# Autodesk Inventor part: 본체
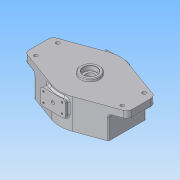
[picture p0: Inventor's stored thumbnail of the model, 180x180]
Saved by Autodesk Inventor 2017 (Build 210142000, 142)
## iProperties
Part Number: 본체
Material: 일반
Document SubType Name: Modeling
Designer: mrc
Density: 1 g/cm^3
Appearance: 기본값
Author: mrc
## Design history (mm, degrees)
sketch "스케치1"
  geometry: L1 (0, 94)-(0, -94); L2 (-24.317, 94)-(24.317, 94); L3 (51.683, 18.811)-(24.317, 94); L4 (-51.683, 18.811)-(-24.317, 94); L5 (-24.317, -94)-(24.317, -94); L6 (51.683, -18.811)-(24.317, -94); L7 (-51.683, -18.811)-(-24.317, -94); L8 (0, 68)-(0, -68); L9 (-33.78, 68)-(33.78, 68); L10 (-33.78, -68)-(33.78, -68); A1 r 55 centre (0, 0) between (-51.683, -18.811) and (51.683, -18.811); A2 r 55 centre (0, 0) between (-51.683, 18.811) and (-51.683, -18.811); A3 r 55 centre (0, 0) between (51.683, 18.811) and (-51.683, 18.811); A4 r 55 centre (0, 0) between (51.683, -18.811) and (51.683, 18.811); 2 further points
  constraints: 20 end point, 11 tangent, 9 point on circle, 5 midpoint, 4 centre point, 4 point on line, 3 horizontal, 2 coincident, 2 vertical, 1 parallel
  dimensions: "d0" = 110 diameter of A1; "d1" = 188 distance of L1.start L1.end; "d2" = 40 deg angle of L3 L4; "d3" = 20 deg angle of L1 L3; "d4" = 40 deg angle of L6 L7; "d5" = 20 deg angle of L1 L6; "d6" = 136 distance of L8.start L8.end; "d7" = 136 distance between parallel lines of L10 L9; "d8" = 26 distance between parallel lines of L5 L10
extrude "돌출1" new body sketch "스케치1" distance "d9" = 15; taper "d10" = 0 deg
extrude "돌출2" join sketch "스케치1" distance "d11" = 55; taper "d12" = 0 deg
sketch "스케치2"
  geometry: L1 (94, 0)-(-94, 0) reference; L2 (-94, 0)-(-94, 15) reference; L3 (-94, 15)-(-68, 15) reference; L4 (-68, 15)-(-68, 55) reference; L5 (-68, 55)-(68, 55) reference; L6 (68, 55)-(68, 15) reference; L7 (68, 15)-(94, 15) reference; L8 (94, 15)-(94, 0) reference; L9 (0, 0)-(0, 55); L10 (-32, 5)-(14, 5); L11 (14, 5)-(14, 35); L12 (14, 35)-(-32, 35); L13 (-32, 35)-(-32, 5); L14 (-32, 5)-(14, 35); L15 (14, 5)-(-32, 35); L16 (-9, 5)-(-9, 35); L17 (14, 20)-(-32, 20)
  constraints: 18 end point, 5 midpoint, 2 parallel, 1 horizontal, 1 perpendicular
  dimensions: "d13" = 46 distance of L12.end L11.end; "d14" = 30 distance of L11.end L10.end; "d122" = 9 distance between parallel lines of L9 L16; "d123" = 20 distance between parallel lines of L1 L17
extrude "돌출3" join sketch "스케치2" stored distance "d16" = 118; taper "d17" = 0 deg
sketch "스케치3"
  geometry: C1 r 17.5 at (0, 0); A1 r 55 centre (0, 0) between (51.683, -18.811) and (51.683, 18.811) reference
  constraints: 2 coincident, 1 centre point
  dimensions: "d18" = 35 diameter of C1
extrude "돌출4" join sketch "스케치3" distance "d20" = 5; taper "d21" = 0 deg
sketch "스케치4"
  geometry: L1 (55, 0)-(-55, 0); A1 r 55 centre (0, 0) between (51.683, -18.811) and (51.683, 18.811) reference; A2 r 55 centre (0, 0) between (-51.683, 18.811) and (-51.683, -18.811) reference; 4 further points
  constraints: 2 end point, 2 point on circle, 2 symmetric about line, 1 horizontal alignment
  dimensions: "d22" = 40 distance of point (20, -79) point (-20, -79); "d23" = 79 vertical distance of A1.centre point (-20, -79); "d24" = 20 horizontal distance of A1.centre point (-20, -79)
hole "구멍1" sketch "스케치4" at (20, -79), (-20, -79), (-20, 79), (20, 79) diameter "d25" = 6.6; stored, may be unused: countersink angle "d29" = 90 deg, drill point angle "d31" = 118 deg; dims "d26" = 6, "d27" = 4, "d28" = 2, "d30" = 8
sketch "스케치5"
  geometry: C1 r 3.3 at (-20, -79) reference; C2 r 3.3 at (20, -79) reference; 1 further point
hole "구멍2" sketch "스케치5" at (20, -79), (-20, -79) diameter "d32" = 11; stored, may be unused: countersink angle "d36" = 90 deg, drill point angle "d38" = 118 deg; dims "d33" = 6, "d34" = 4, "d35" = 2, "d37" = 6.6
sketch "스케치6"
  geometry: C1 r 3.3 at (20, 79) reference; C2 r 3.3 at (-20, 79) reference; 1 further point
hole "구멍3" sketch "스케치6" at (20, 79), (-20, 79) diameter "d39" = 11; stored, may be unused: countersink angle "d43" = 90 deg, drill point angle "d45" = 0 deg; dims "d40" = 6, "d41" = 4, "d42" = 2, "d44" = 6.6
sketch "스케치7"
  geometry: L1 (5, 14)-(5, -32) reference; L2 (11, -26)-(29, -26); L3 (29, -26)-(29, 8); L4 (29, 8)-(11, 8); L5 (11, 8)-(11, -26); L6 (11, -26)-(29, 8); L7 (29, -26)-(11, 8); L8 (29, -9)-(11, -9); L9 (20, -26)-(20, 8); 5 further points
  constraints: 16 end point, 4 coincident, 4 midpoint, 2 parallel, 1 horizontal, 1 perpendicular
  dimensions: "d46" = 18 distance of L4.end L3.end; "d47" = 34 distance of L3.end L2.end; "d48" = 6 distance between parallel lines of L1 L5; "d124" = 9 distance from line of point (0, 0) L8
hole "구멍4" sketch "스케치7" at (11, -26), (11, 8), (29, 8), (29, -26) diameter "d49" = 3.242; stored, may be unused: countersink angle "d53" = 90 deg, drill point angle "d55" = 118 deg; dims "d50" = 8, "d51" = 4, "d52" = 2, "d54" = 10
sketch "스케치8"
  geometry: L1 (55, 0)-(-55, 0); A1 r 55 centre (0, 0) between (-51.683, 18.811) and (-51.683, -18.811) reference; A2 r 55 centre (0, 0) between (51.683, -18.811) and (51.683, 18.811) reference; 4 further points
  constraints: 2 end point, 2 point on circle, 2 symmetric about line
  dimensions: "d56" = 50 distance of point (-25, -61) point (25, -61); "d57" = 25 horizontal distance of A1.centre point (-25, -61); "d58" = 61 vertical distance of A1.centre point (-25, -61)
hole "구멍5" sketch "스케치8" at (25, -61), (-25, -61), (-25, 61), (25, 61) diameter "d59" = 4.917; stored, may be unused: countersink angle "d63" = 90 deg, drill point angle "d65" = 118 deg; dims "d60" = 12, "d61" = 4, "d62" = 2, "d64" = 14
sketch "스케치9"
  geometry: L1 (68, 55)-(68, 15) reference; L2 (68, 15)-(94, 15) reference; L3 (94, 15)-(94, 0) reference; L4 (94, 0)-(17.5, 0) reference; L5 (17.5, 0)-(17.5, -5) reference; L6 (17.5, -5)-(-17.5, -5) reference; L7 (-17.5, -5)-(-17.5, 0) reference; L8 (-17.5, 0)-(-94, 0) reference; L9 (-94, 0)-(-94, 15) reference; L10 (-94, 15)-(-68, 15) reference; L11 (-68, 15)-(-68, 55) reference; L12 (-68, 55)-(68, 55) reference; L13 (18.811, 55)-(-18.811, 55) reference; L14 (0, 55)-(0, 25); L15 (0, 55)-(-40, 55); L16 (-68, 55)-(-18.811, 55) reference; L17 (-40, 55)-(-40, 25); L18 (-40, 25)-(0, 25); 1 further point
  constraints: 8 end point, 2 perpendicular, 1 midpoint, 1 point on line, 1 vertical
  dimensions: "d66" = 30 distance of L14.start L14.end; "d67" = 40 distance of L14.start L15.end
revolve "회전1" sketch "스케치9" stored, may be unused: angle "d68" = 90 deg
sketch "스케치10"
  geometry: L1 (68, 55)-(68, 15) reference; L2 (68, 15)-(94, 15) reference; L3 (94, 15)-(94, 0) reference; L4 (94, 0)-(17.5, 0) reference; L5 (17.5, 0)-(17.5, -5) reference; L6 (17.5, -5)-(-17.5, -5) reference; L7 (-17.5, -5)-(-17.5, 0) reference; L8 (-17.5, 0)-(-94, 0) reference; L9 (-94, 0)-(-94, 15) reference; L10 (-94, 15)-(-68, 15) reference; L11 (-68, 15)-(-68, 55) reference; L12 (-68, 55)-(-40, 55) reference; L13 (-40, 55)-(-40, 25) reference; L14 (-40, 25)-(40, 25) reference; L15 (40, 25)-(40, 55) reference; L16 (40, 55)-(68, 55) reference; L17 (0, 25)-(0, -5); L18 (0, 25)-(-10, 25); L19 (40, 25)-(-40, 25) reference; L20 (-10, 25)-(-10, 15); L21 (-10, 15)-(-8, 15); L22 (-8, 15)-(-8, 3.4); L23 (-8, 3.4)-(-12.5, 3.4); L24 (-12.5, 3.4)-(-12.5, -5); L25 (-12.5, -5)-(0, -5); 1 further point
  constraints: 16 end point, 5 perpendicular, 2 midpoint, 2 point on line, 2 vertical
  dimensions: "d71" = 20 diameter of L20 L17; "d72" = 16 diameter of L22 L17; "d73" = 10 distance of L18.end L20.end; "d74" = 25 diameter of L24 L17; "d75" = 8.4 distance of L23.end L24.end
revolve "회전2" sketch "스케치10" stored, may be unused: angle "d76" = 90 deg
sketch "스케치11"
  geometry: C1 r 10 at (0, 0) reference; C2 r 40 at (0, 0) reference; 2 further points
  constraints: 1 horizontal alignment
  dimensions: "d77" = 30 distance of point (15, -26) point (-15, -26); "d78" = 15 horizontal distance of C2.centre point (15, -26); "d79" = 26 vertical distance of C1.centre point (15, -26)
hole "구멍6" sketch "스케치11" at (15, -26), (-15, -26) diameter "d80" = 3.242; stored, may be unused: countersink angle "d84" = 90 deg, drill point angle "d86" = 118 deg; dims "d81" = 8, "d82" = 4, "d83" = 2, "d85" = 10
sketch "스케치14"
  geometry: C1 r 47.5 at (0, 0); C2 r 43.4 at (0, 0); A1 r 55 centre (0, 0) between (51.683, -18.811) and (51.683, 18.811) reference
  constraints: 2 centre point, 1 coincident
  dimensions: "d99" = 95 diameter of C1; "d100" = 4.1 radial gap between concentric circles of C1 C2
extrude "돌출7" cut sketch "스케치14" distance "d101" = 2.4; taper "d102" = 0 deg
fillet "모깎기1" dims "d103" = 10
chamfer "모따기1" distance "d106" = 1; stored, may be unused: second distance "d107" = 2, angle "d108" = 45 deg
fillet "모깎기4" dims "d109" = 0.5
fillet "모깎기5" dims "d110" = 5
fillet "모깎기6" dims "d111" = 0.2
chamfer "모따기2" distance "d112" = 0.4; stored, may be unused: second distance "d113" = 2, angle "d114" = 30 deg
fillet "모깎기7" dims "d115" = 3
fillet "모깎기8" dims "d116" = 3
fillet "모깎기9" dims "d117" = 3
sketch "스케치15" dims "d11" = 55
  geometry: L1 (0, 37)-(63.358, 37) reference; L2 (56.567, 18.398)-(6.792, 18.398); L3 (6.792, 18.398)-(6.792, 25.602); L4 (6.792, 25.602)-(56.567, 25.602); L5 (56.567, 25.602)-(56.567, 18.398); L6 (56.567, 22)-(6.792, 22); L7 (31.679, 18.398)-(31.679, 25.602); L8 (90.679, 12)-(90.679, -8) reference; 1 further point
  constraints: 4 end point, 4 midpoint, 2 other
  dimensions: "d118" = 59 distance between parallel lines of L8 L7; "d119" = 15 distance between parallel lines of L1 L6
feature "엠보싱1" sketch "스케치15" dims "d0" = 110, "d1" = 188, "d2" = 40 deg, "d3" = 20 deg, "d4" = 40 deg, "d5" = 20 deg, "d7" = 136, "d8" = 26, "d120" = 0.5, "d121" = 0
sketch "스케치16"
  geometry: L1 (59, 9)-(59, -27) reference; L2 (59, -9)-(-59, -9); L3 (-59, 9)-(-59, -27) reference; L4 (28.373, -15)-(18.735, -15); L5 (28.373, -3)-(23.812, -3); L6 (18.735, -15)-(-18.735, -15); L7 (-18.735, -15)-(-28.373, -15); L8 (-23.812, -3)-(-28.373, -3); L9 (23.812, -3)-(-23.812, -3); C1 r 40 at (0, 0) reference; A1 r 24 centre (0, 0) between (23.812, -3) and (-23.812, -3); A2 r 29 centre (0, -9) between (28.373, -3) and (-28.373, -3); A3 r 24 centre (0, 0) between (22.249, -9) and (23.812, -3); A4 r 29 centre (0, -9) between (29, -9) and (28.373, -3); A5 r 29 centre (0, -9) between (28.373, -15) and (29, -9); A6 r 24 centre (0, 0) between (-18.735, -15) and (18.735, -15); A7 r 24 centre (0, 0) between (-23.812, -3) and (-18.735, -15); A8 r 29 centre (0, -9) between (-28.373, -15) and (28.373, -15); A9 r 29 centre (0, -9) between (-28.373, -3) and (-28.373, -15); A10 r 24 centre (0, 0) between (18.735, -15) and (22.249, -9)
  constraints: 25 point on circle, 14 end point, 10 centre point, 3 horizontal, 3 midpoint, 2 point on line, 1 coincident
  dimensions: "d127" = 48 diameter of A1; "d128" = 58 diameter of A2; "d129" = 12 distance between parallel lines of L4 L5; "d130" = 6 distance between parallel lines of L4 L2
extrude "돌출8" cut sketch "스케치16" distance "d131" = 12; taper "d132" = 0 deg
fillet "모깎기10" dims "d133" = 2
fillet "모깎기11" dims "d134" = 2
sketch "스케치17" dims "d27" = 4
  geometry: L1 (35, -27)-(35, 9) reference; L2 (5, 9)-(5, -27) reference; L3 (35, -9)-(5, -9); L4 (5, 9)-(5, -19.837) reference; C1 r 3 at (20, -9); 1 further point
  constraints: 2 end point, 2 midpoint, 1 centre point, 1 perpendicular, 1 point on line
  dimensions: "d135" = 6 diameter of C1
extrude "돌출9" cut sketch "스케치17" stored distance "d136" = 12; taper "d137" = 0 deg
node "솔리드1"
mirror "미러1"
mirror "미러3"
node "절단 모서리 투영1"
node "절단 모서리 투영2"
node "절단 모서리 투영3"
other parameters: "d89" = 12, "d90" = 6
